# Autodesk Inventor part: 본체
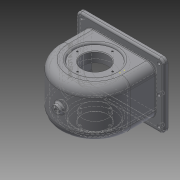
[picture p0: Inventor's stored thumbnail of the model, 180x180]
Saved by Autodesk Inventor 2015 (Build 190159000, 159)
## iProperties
Created: 2015-09
Part Number: 본체
Material: 일반
Document SubType Name: Modeling
Designer: Administrator
Density: 1 g/cm^3
Appearance: 기본값
Author: Administrator
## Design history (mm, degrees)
sketch "스케치1"
  geometry: L1 (63, 52)-(-63, 52); L2 (-70, 45)-(-70, -45); L3 (-63, -52)-(63, -52); L4 (70, -45)-(70, 45); A1 r 7 centre (63, 45) between (70, 45) and (63, 52); A2 r 7 centre (-63, 45) between (-63, 52) and (-70, 45); A3 r 7 centre (-63, -45) between (-70, -45) and (-63, -52); A4 r 7 centre (63, -45) between (63, -52) and (70, -45); 5 further points
  constraints: 8 end point, 8 point on circle, 8 tangent, 6 point on line, 4 centre point, 3 equal radius, 2 parallel, 1 horizontal, 1 perpendicular
  dimensions: "d0" = 104 distance of point (70, -52) point (70, 52); "d1" = 140 distance of point (70, 52) point (-70, 52); "d2" = 7 radius of A1
extrude "돌출1" new body sketch "스케치1" distance "d3" = 7; taper "d4" = 0 deg
sketch "스케치2"
  geometry: 1 further point
sketch "스케치13"
  geometry: L1 (63, 52)-(-63, 52) reference; L2 (70, -45)-(70, 45) reference; L3 (-63, -52)-(63, -52) reference; L4 (62, 52)-(62, 44); L5 (62, 44)-(62, 0); L6 (62, 0)-(62, -44); L7 (0, 52)-(0, -52); C1 r 2.5 at (62, 44); C2 r 2.5 at (62, 0); C3 r 2.5 at (62, -44); C4 r 2.5 at (-62, 44); C5 r 2.5 at (-62, 0); C6 r 2.5 at (-62, -44); 1 further point
  constraints: 8 end point, 6 centre point, 3 coincident, 3 symmetric about line, 2 midpoint, 2 point on line, 2 vertical, 3 other
  dimensions: "d30" = 8 distance of L4.start L4.end; "d31" = 5 diameter of C1; "d32" = 44 distance of L5.start L5.end; "d33" = 44 distance of L5.end L6.end; "d34" = 5 diameter of C2; "d35" = 5 diameter of C3
extrude "돌출8" cut sketch "스케치13" stored distance "d36" = 7; taper "d37" = 0 deg
sketch "스케치15"
  geometry: L1 (-63, 7)-(63, 7) reference; L2 (0, 7)-(0, -97); L3 (0, 7)-(0, -40); L4 (-57, -40)-(-57, 0); L5 (57, -40)-(57, 0); L6 (-57, 0)-(57, 0); L7 (63, 0)-(-63, 0) reference; A1 r 57 centre (0, -40) between (-57, -40) and (57, -40); 1 further point
  constraints: 10 end point, 3 point on circle, 3 vertical, 1 centre point, 1 coincident, 1 collinear, 1 midpoint, 1 point on line, 1 tangent
  dimensions: "d40" = 104 distance of L2.start L2.end; "d41" = 47 distance of L2.start L3.end
extrude "돌출9" join sketch "스케치15" stored distance "d42" = 77; taper "d43" = 0 deg
sketch "스케치16"
  geometry: 1 further point
feature "쉘2" dims "d46" = 5
sketch "스케치17"
  geometry: L1 (120.126, 84.126)-(120.126, 53.874) reference; L2 (107.126, 80.5)-(3.126, 80.5) reference; L3 (107.126, 13.5)-(107.126, 80.5) reference; L4 (3.126, 13.5)-(107.126, 13.5) reference; L5 (3.126, 80.5)-(3.126, 13.5) reference; L6 (-9.874, 53.874)-(-9.874, 84.126) reference; L7 (-9.874, 9.874)-(-9.874, 40.126) reference; L8 (110.252, 0)-(0, 0) reference; L9 (120.126, 40.126)-(120.126, 9.874) reference; L10 (120.126, 84.126)-(120.126, 53.874) reference; L11 (0, 94)-(110.252, 94) reference; A1 r 7.5 centre (-6.874, 91) between (-9.874, 84.126) and (0, 94) reference; A2 r 7.5 centre (-6.874, 47) between (-9.874, 40.126) and (-9.874, 53.874) reference; A3 r 7.5 centre (-6.874, 3) between (0, 0) and (-9.874, 9.874) reference; A4 r 7.5 centre (117.126, 3) between (120.126, 9.874) and (110.252, 0) reference; A5 r 7.5 centre (117.126, 47) between (120.126, 53.874) and (120.126, 40.126) reference; A6 r 7.5 centre (117.126, 91) between (110.252, 94) and (120.126, 84.126) reference; 1 further point
extrude "돌출11" join sketch "스케치17" stored distance "d47" = 5; taper "d48" = 0 deg
node "작업 평면2"
sketch "스케치18"
  geometry: C1 r 6 at (0, 0); 1 further point
  constraints: 1 centre point, 1 coincident
  dimensions: "d50" = 12 diameter of C1
extrude "돌출12" join sketch "스케치18" distance "d51" = 12 (= d50); taper "d52" = 10 deg
sketch "스케치19"
  geometry: L1 (-63, 7)-(63, 7) reference; L2 (0, 7)-(0, -40); C1 r 31 at (0, -40); 1 further point
  constraints: 2 end point, 1 centre point, 1 coincident, 1 midpoint, 1 vertical
  dimensions: "d53" = 47 distance of L2.start L2.end; "d54" = 62 diameter of C1
extrude "돌출13" join sketch "스케치19" distance "d55" = 10; taper "d56" = 0 deg
sketch "스케치20"
  geometry: C1 r 20 at (0, 0); 1 further point
  constraints: 1 centre point
  dimensions: "d57" = 40 diameter of C1
extrude "돌출14" cut sketch "스케치20" stored distance "d58" = 10; taper "d59" = 0 deg
sketch "스케치22"
  geometry: L1 (-40, 38.5)-(-97, 38.5) reference; L2 (7, 2.5)-(7, -2.5) reference; L3 (7, 0)-(-40, 0); L4 (-40, 33.5)-(-40, 19.5); L5 (-68, 19.5)-(-40, 19.5); L6 (-68, 19.5)-(-79.747, 33.5); L7 (-40, 19.5)-(-40, 33.5); L8 (-40, 33.5)-(-92, 33.5) reference; L9 (-79.747, 33.5)-(-40, 33.5); 1 further point
  constraints: 12 end point, 3 point on line, 1 horizontal, 1 midpoint, 1 perpendicular
  dimensions: "d61" = 47 distance of L3.start L3.end
revolve "회전1" sketch "스케치22" stored, may be unused: angle "d67" = 90 deg
sketch "스케치23"
  geometry: L1 (-52, 7)-(52, 7) reference; L2 (0, 7)-(0, -40); C1 r 33 at (0, -40); 1 further point
  constraints: 2 end point, 1 centre point, 1 coincident, 1 midpoint, 1 vertical
  dimensions: "d68" = 47 distance of L2.start L2.end; "d69" = 66 diameter of C1
extrude "돌출15" cut sketch "스케치23" distance "d70" = 3; taper "d71" = 0 deg
sketch "스케치24"
  geometry: C1 r 20 at (0, 0); 1 further point
  constraints: 1 centre point
  dimensions: "d72" = 40 diameter of C1
extrude "돌출16" cut sketch "스케치24" distance "d73" = 16; taper "d74" = 0 deg
sketch "스케치25"
  geometry: L1 (-38.5, 47.613)-(-38.5, 17.613); 2 further points
  constraints: 2 end point, 1 vertical, 1 other
  dimensions: "d75" = 30 distance of L1.start L1.end
feature "엠보싱1" sketch "스케치25" dims "d0" = 104, "d1" = 140, "d2" = 7, "d76" = 0.5, "d77" = 0
sketch "스케치26"
  geometry: 2 further points
hole "구멍1" sketch "스케치26" at (0.204, -27.999) diameter "d79" = 2.459; stored, may be unused: countersink angle "d83" = 90 deg, drill point angle "d85" = 118 deg; dims "d80" = 7, "d81" = 4, "d82" = 2, "d84" = 9
sketch "스케치27" dims "d90" = 48
  geometry: L1 (-52, 47)-(52, 47) reference; L2 (0, 47)-(0, 0); 3 further points
  constraints: 2 end point, 1 coincident, 1 midpoint, 1 vertical, 1 vertical alignment, 2 other
  dimensions: "d89" = 47 distance of L2.start L2.end
hole "구멍2" sketch "스케치27" at (0, -24) diameter "d91" = 2.459; stored, may be unused: countersink angle "d95" = 90 deg, drill point angle "d97" = 118 deg; dims "d92" = 6, "d93" = 4, "d94" = 2, "d96" = 8
hole "구멍3" diameter "d103" = 4.459; stored, may be unused: countersink angle "d107" = 90 deg, drill point angle "d109" = 118 deg; dims "d101" = 10, "d102" = 10, "d104" = 20, "d105" = 4, "d106" = 2, "d108" = 20
fillet "모깎기1" dims "d110" = 3, "d111" = 14
fillet "모깎기2" dims "d112" = 1, "d113" = 3, "d114" = 9
chamfer "모따기1" distance "d115" = 1; stored, may be unused: second distance "d116" = 2, angle "d117" = 45 deg
chamfer "모따기2" distance "d118" = 1; stored, may be unused: second distance "d119" = 2, angle "d120" = 45 deg
fillet "모깎기3" dims "d121" = 3
node "솔리드1"
pattern_circular "원형 패턴1" dims angle "d87" = 360 deg
pattern_circular "원형 패턴2" dims angle "d99" = 360 deg
node "투영된 루프1"
